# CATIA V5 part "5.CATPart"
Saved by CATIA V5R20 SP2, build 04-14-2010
Part number: 5
Bounding box of the stored display mesh (mm): x -150 to 150, y -25 to 572, z -39.99 to 39.99
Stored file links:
  C:\Users\Orange\Desktop\Assembly Design-14\5.CATPart
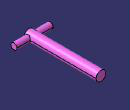
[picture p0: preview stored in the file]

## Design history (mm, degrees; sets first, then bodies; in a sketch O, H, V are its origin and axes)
Body1 (main body)
  Sketch1 on yz-plane, origin (0, 0, 0), H (0, 1, 0), V (0, 0, 1)
    circle A1 centre (0, 0) radius 25
  Pad1: profile Sketch1, direction (1, 0, 0), length 150, mirrored extent
  Sketch2 on zx-plane, origin (0, 0, 0), H (-1, 0, 0), V (0, 0, 1)
    circle A1 centre (0, 0) radius 40
  Pad2: profile Sketch2, direction (0, 1, 0), length 572, opposite side length 25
